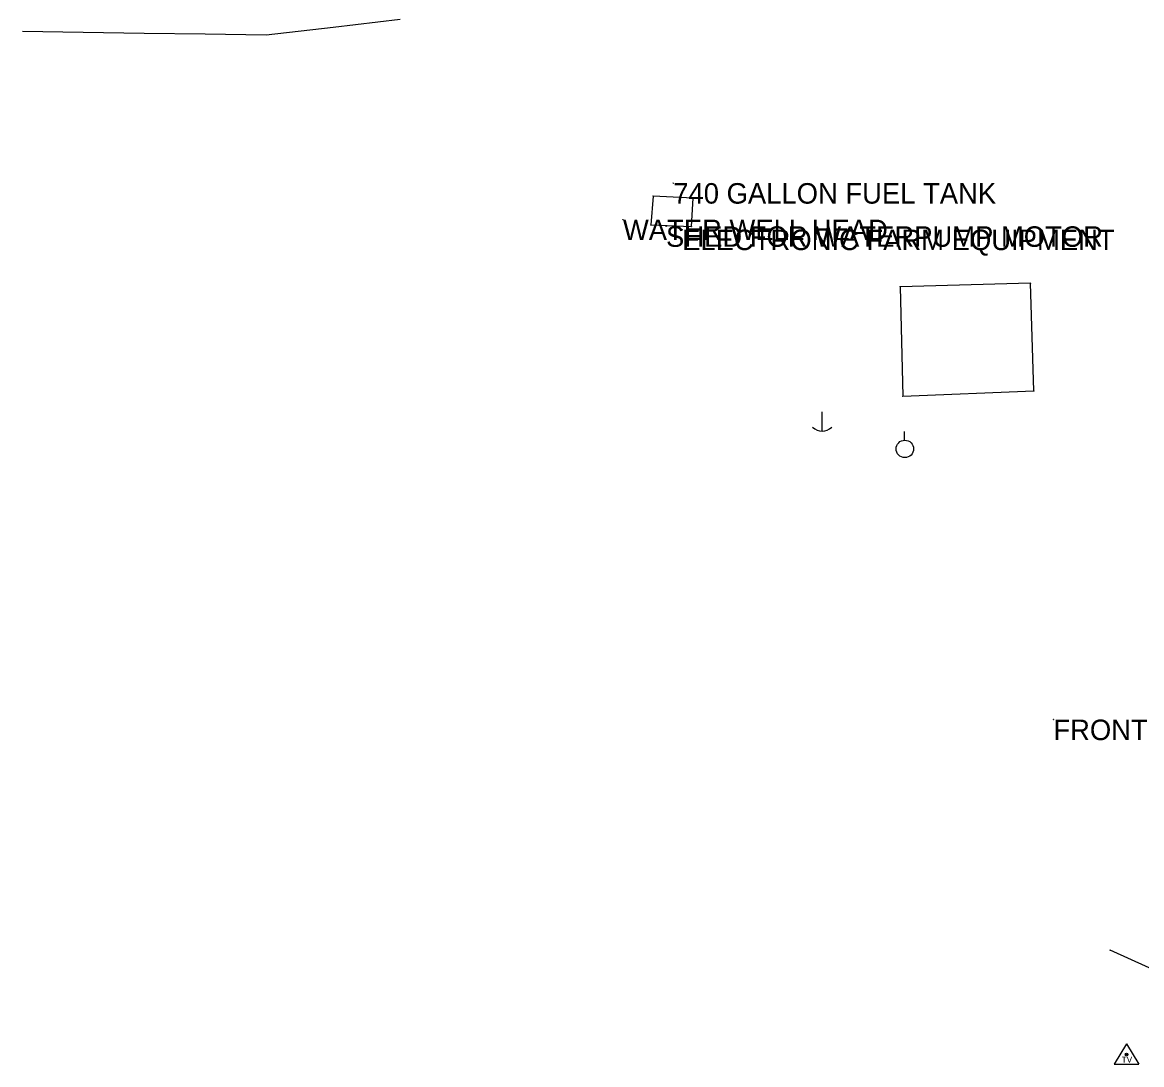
# Model space of a CAD drawing. Extents: x 1804576 to 1805329, y 515859 to 519427.
# Drawn here: x 1804575.6 to 1804848.7, y 517477.4 to 517731.6 of the extents above; entities that cross this region are included whole.
import ezdxf

# ---------------------------------------------------------------- set-up
doc = ezdxf.new("R2010")
doc.units = 0
for name, color, linetype in [('S_BUILDING', 7, 'Continuous'), ('S_MSC_PT_SYM', 7, 'Continuous'), ('S_SECONDARY_CTL', 7, 'Continuous'), ('S_STR_PT_SYM', 7, 'Continuous'), ('S_STREAM', 7, 'Continuous'), ('S_SURVEY_TEXT_ANNOT', 7, 'Continuous'), ('S_UTILITY_POLE', 7, 'Continuous'), ('S_UTL_PT_SYM', 7, 'Continuous'), ('S_WATER_UTILITIES', 7, 'Continuous')]:
    doc.layers.add(name, color=color, linetype=linetype)

msp = doc.modelspace()

# ---------------------------------------------------------------- linework, layer by layer
at = {"layer": 'S_BUILDING'}
for p, q in [((1804729.48, 517689.25), (1804728.93, 517682.19)), ((1804739.3, 517688.74), (1804729.48, 517689.25)), ((1804738.83, 517681.84), (1804739.3, 517688.74)), ((1804728.93, 517682.19), (1804738.83, 517681.84)), ((1804821.62, 517667.98), (1804789.74, 517667.12)), ((1804789.74, 517667.12), (1804790.41, 517640.41)), ((1804822.42, 517641.69), (1804821.62, 517667.98)), ((1804790.41, 517640.41), (1804822.42, 517641.69))]:
    msp.add_line(p, q, dxfattribs=at)
at = {"layer": 'S_MSC_PT_SYM'}
for points in [[(1804734.42, 517692.4), (1804734.42, 517692.45), (1804734.42, 517692.4), (1804734.37, 517692.4), (1804734.42, 517692.4), (1804734.42, 517692.35), (1804734.42, 517692.4), (1804734.47, 517692.4)], [(1804722.13, 517683.49), (1804722.13, 517683.54), (1804722.13, 517683.49), (1804722.08, 517683.49), (1804722.13, 517683.49), (1804722.13, 517683.44), (1804722.13, 517683.49), (1804722.18, 517683.49)], [(1804732.65, 517681.86), (1804732.65, 517681.91), (1804732.65, 517681.86), (1804732.6, 517681.86), (1804732.65, 517681.86), (1804732.65, 517681.81), (1804732.65, 517681.86), (1804732.7, 517681.86)], [(1804736.6, 517681.06), (1804736.6, 517681.11), (1804736.6, 517681.06), (1804736.55, 517681.06), (1804736.6, 517681.06), (1804736.6, 517681.01), (1804736.6, 517681.06), (1804736.65, 517681.06)], [(1804827.16, 517561.52), (1804827.16, 517561.57), (1804827.16, 517561.52), (1804827.11, 517561.52), (1804827.16, 517561.52), (1804827.16, 517561.47), (1804827.16, 517561.52), (1804827.21, 517561.52)]]:
    msp.add_lwpolyline(points, dxfattribs=at)
at = {"layer": 'S_SECONDARY_CTL'}
for p, q in [((1804845.03, 517482.44), (1804842.02, 517477.49)), ((1804845.03, 517482.44), (1804847.98, 517477.49)), ((1804842.02, 517477.49), (1804847.98, 517477.49))]:
    msp.add_line(p, q, dxfattribs=at)
for radius in [0.311, 0.183, 0.103]:
    msp.add_circle((1804845.03, 517479.83), radius, dxfattribs=at)
at = {"layer": 'S_STR_PT_SYM'}
for points in [[(1804729.48, 517689.25), (1804729.48, 517689.3), (1804729.48, 517689.25), (1804729.43, 517689.25), (1804729.48, 517689.25), (1804729.48, 517689.2), (1804729.48, 517689.25), (1804729.53, 517689.25)], [(1804739.3, 517688.74), (1804739.3, 517688.79), (1804739.3, 517688.74), (1804739.25, 517688.74), (1804739.3, 517688.74), (1804739.3, 517688.69), (1804739.3, 517688.74), (1804739.35, 517688.74)], [(1804728.93, 517682.19), (1804728.93, 517682.24), (1804728.93, 517682.19), (1804728.88, 517682.19), (1804728.93, 517682.19), (1804728.93, 517682.14), (1804728.93, 517682.19), (1804728.98, 517682.19)], [(1804738.83, 517681.84), (1804738.83, 517681.89), (1804738.83, 517681.84), (1804738.78, 517681.84), (1804738.83, 517681.84), (1804738.83, 517681.79), (1804738.83, 517681.84), (1804738.88, 517681.84)], [(1804789.74, 517667.12), (1804789.74, 517667.17), (1804789.74, 517667.12), (1804789.69, 517667.12), (1804789.74, 517667.12), (1804789.74, 517667.07), (1804789.74, 517667.12), (1804789.79, 517667.12)], [(1804821.62, 517667.98), (1804821.62, 517668.03), (1804821.62, 517667.98), (1804821.57, 517667.98), (1804821.62, 517667.98), (1804821.62, 517667.93), (1804821.62, 517667.98), (1804821.67, 517667.98)], [(1804822.42, 517641.69), (1804822.42, 517641.74), (1804822.42, 517641.69), (1804822.37, 517641.69), (1804822.42, 517641.69), (1804822.42, 517641.64), (1804822.42, 517641.69), (1804822.47, 517641.69)], [(1804790.41, 517640.41), (1804790.41, 517640.46), (1804790.41, 517640.41), (1804790.36, 517640.41), (1804790.41, 517640.41), (1804790.41, 517640.36), (1804790.41, 517640.41), (1804790.46, 517640.41)]]:
    msp.add_lwpolyline(points, dxfattribs=at)
at = {"layer": 'S_STREAM'}
msp.add_lwpolyline([(1804667.78, 517732.33), (1804651.43, 517730.4), (1804635.08, 517728.47), (1804620.21, 517728.7), (1804605.34, 517728.93), (1804590.47, 517729.16), (1804575.6, 517729.39)], dxfattribs=at)
at = {"layer": 'S_UTILITY_POLE'}
for p, q in [((1804770.69, 517636.64), (1804770.69, 517631.91)), ((1804790.81, 517629.7), (1804790.81, 517631.81))]:
    msp.add_line(p, q, dxfattribs=at)
msp.add_circle((1804790.93, 517627.56), 2.13, dxfattribs=at)
msp.add_arc((1804770.75, 517635.33), 3.41, 226.3972, 313.6028, dxfattribs=at)
at = {"layer": 'S_UTL_PT_SYM'}
msp.add_lwpolyline([(1804841.05, 517505.28), (1804841.05, 517505.33), (1804841.05, 517505.28), (1804841, 517505.28), (1804841.05, 517505.28), (1804841.05, 517505.23), (1804841.05, 517505.28), (1804841.1, 517505.28)], dxfattribs=at)
at = {"layer": 'S_WATER_UTILITIES'}
msp.add_line((1804902.33, 517477.35), (1804841.05, 517505.28), dxfattribs=at)

# ---------------------------------------------------------------- texts
at = {"layer": 'S_SECONDARY_CTL'}
msp.add_text('TV', height=1.5, dxfattribs=at).set_placement((1804843.83, 517477.82))
at = {"layer": 'S_SURVEY_TEXT_ANNOT'}
for s, p in [('740 GALLON FUEL TANK', (1804734.42, 517687.4)), ('WATER WELL HEAD', (1804722.13, 517678.49)), ('SHED FOR WATERPUMP MOTOR', (1804732.65, 517676.86)), ('ELECTRONIC FARM EQUIPMENT', (1804736.6, 517676.06)), ('FRONT OF NEW HOME CONSTRU', (1804827.16, 517556.52))]:
    msp.add_text(s, height=5, dxfattribs=at).set_placement(p)

doc.saveas('drawing.dxf')
